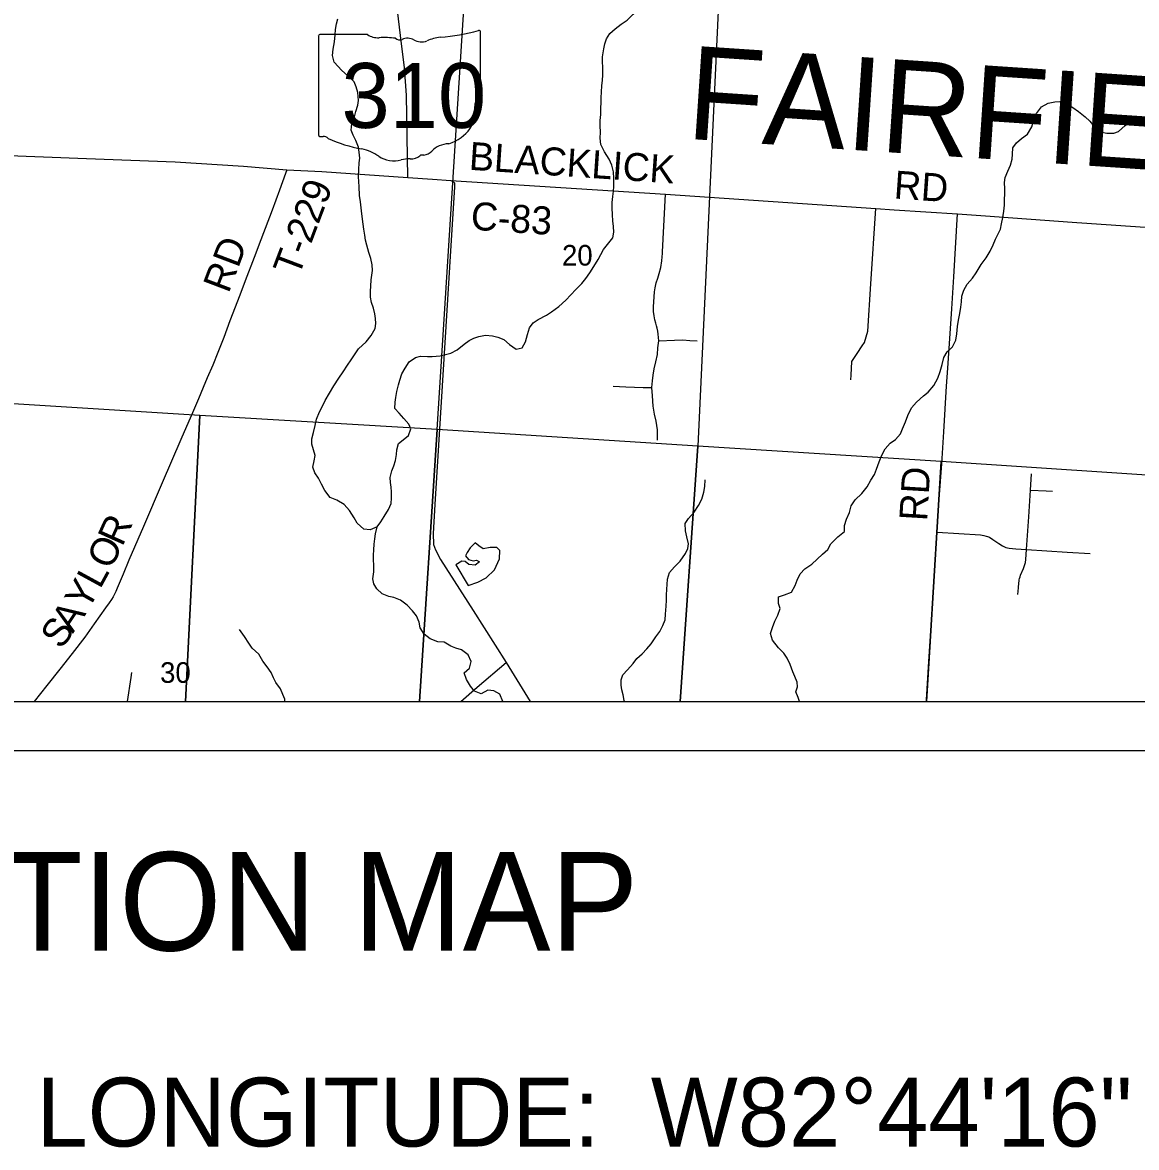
# Model space of a CAD drawing. Extents: x 0 to 34, y 0 to 22.
# Drawn here: x 5.197 to 7.46, y 13.194 to 15.479 of the extents above; entities that cross this region are included whole.
import ezdxf

# ---------------------------------------------------------------- set-up
doc = ezdxf.new("R2010")
doc.units = 0
for name, color, linetype in [('GM_X_Corporation', 7, 'Continuous'), ('GM_X_County_Road', 7, 'Continuous'), ('GM_X_County_Road_Text', 7, 'Continuous'), ('GM_X_County_Text', 7, 'Continuous'), ('GM_X_Minor_Lake', 7, 'Continuous'), ('GM_X_Minor_River', 7, 'Continuous'), ('GM_X_Section', 7, 'Continuous'), ('GM_X_Section_Text', 7, 'Continuous'), ('GM_X_State_Location', 7, 'Continuous'), ('GM_X_State_Route', 7, 'Continuous'), ('GM_X_State_Shield', 7, 'Continuous'), ('GM_X_Township_Road', 7, 'Continuous'), ('GM_X_Township_Road_Text', 7, 'Continuous'), ('GM_X_Unincorporated_Text', 7, 'Continuous'), ('SH_Cut_Line', 7, 'Continuous'), ('SH_Data', 7, 'Continuous'), ('SH_Text', 7, 'Continuous')]:
    doc.layers.add(name, color=color, linetype=linetype)

msp = doc.modelspace()

# ---------------------------------------------------------------- linework, layer by layer
at = {"layer": 'GM_X_Corporation'}
msp.add_lwpolyline([(4.9875, 14.1), (8.9, 14.1), (8.9, 15.4827), (8.6741, 15.4976), (7.6503, 15.5653), (6.838, 15.6206), (6.624, 15.6351), (6.4, 15.6498), (6.1109, 15.6683), (5.9419, 15.6782), (5.0952, 15.7318), (5.0611, 15.2147)], close=True, dxfattribs=at)
at = {"layer": 'GM_X_County_Road'}
msp.add_lwpolyline([(6.0671, 15.1581), (6.5033, 15.13), (6.9303, 15.1012), (6.9673, 15.0987), (7.0963, 15.09), (7.1532, 15.0863), (7.3292, 15.0734), (7.3386, 15.0729), (7.3489, 15.0722), (7.5961, 15.0553), (7.606, 15.0546), (7.6158, 15.0539), (7.8422, 15.0387), (7.8505, 15.0381), (7.8619, 15.0373), (8.1079, 15.0203), (8.1178, 15.0196), (8.3992, 15.0045), (8.635, 14.9861)], dxfattribs=at)
at = {"layer": 'GM_X_Minor_Lake'}
for points in [[(6.102, 14.3357), (6.1218, 14.3423), (6.1389, 14.3513), (6.1554, 14.367), (6.1658, 14.3893), (6.1664, 14.4064), (6.16, 14.4129), (6.1468, 14.4123), (6.1323, 14.4102), (6.1237, 14.416), (6.1162, 14.4221), (6.1062, 14.412), (6.1001, 14.4025), (6.0966, 14.3954), (6.1026, 14.3881), (6.112, 14.3857), (6.1188, 14.3872), (6.1249, 14.3833), (6.1161, 14.3769), (6.1032, 14.3782), (6.0957, 14.384), (6.0889, 14.3848), (6.0771, 14.3777)], [(6.0771, 14.3777), (6.102, 14.3357)]]:
    msp.add_lwpolyline(points, dxfattribs=at)
at = {"layer": 'GM_X_Minor_River'}
for points in [[(6.3752, 15.3987), (6.3749, 15.409), (6.3774, 15.4253), (6.3798, 15.4355), (6.3833, 15.4457), (6.3902, 15.4563), (6.4009, 15.466), (6.4132, 15.4758), (6.4254, 15.484), (6.4372, 15.496), (6.4472, 15.5043), (6.4594, 15.514), (6.4603, 15.5269), (6.4574, 15.5379), (6.4556, 15.5482), (6.455, 15.5592), (6.4547, 15.5687), (6.4544, 15.579), (6.4549, 15.5892), (6.4554, 15.5987), (6.4548, 15.6101), (6.4534, 15.6204), (6.448, 15.6404)], [(5.9173, 14.4545), (5.9028, 14.4482), (5.8903, 14.4499), (5.8764, 14.4618), (5.8705, 14.4729), (5.8608, 14.4878), (5.8503, 14.5), (5.8349, 14.5085), (5.8217, 14.5144), (5.8109, 14.5282), (5.8042, 14.5415), (5.7979, 14.5533), (5.7908, 14.5644), (5.7867, 14.5755), (5.7892, 14.5887), (5.7912, 14.5993), (5.7875, 14.6111), (5.7842, 14.6226), (5.7847, 14.6336), (5.7879, 14.6464), (5.7915, 14.6604), (5.7942, 14.6733), (5.7997, 14.6881), (5.8051, 14.6983), (5.8117, 14.7111), (5.8202, 14.7262), (5.8291, 14.7409), (5.8395, 14.7564), (5.8483, 14.7692), (5.8572, 14.7831), (5.8645, 14.7941), (5.8722, 14.8057), (5.8795, 14.8163), (5.8948, 14.8306), (5.9052, 14.8434), (5.9129, 14.8577), (5.9145, 14.8679), (5.9135, 14.8774), (5.9121, 14.8869), (5.9099, 14.8987), (5.9059, 14.9102), (5.9037, 14.9212), (5.9035, 14.9333), (5.904, 14.9432), (5.9053, 14.9565), (5.9065, 14.9659), (5.9074, 14.9754), (5.9067, 14.9868), (5.9042, 14.9998), (5.9005, 15.0116), (5.8962, 15.0264), (5.8936, 15.0371), (5.8918, 15.0469), (5.8901, 15.0595), (5.8887, 15.069), (5.8876, 15.0796), (5.8852, 15.0967), (5.8831, 15.115), (5.8813, 15.1275), (5.8804, 15.1461), (5.8797, 15.1556), (5.8791, 15.1663), (5.88, 15.1807), (5.8809, 15.1936), (5.8818, 15.2034), (5.8804, 15.2156), (5.879, 15.2259), (5.8735, 15.2396), (5.8683, 15.2503), (5.8642, 15.2602), (5.8659, 15.2735), (5.8705, 15.2844), (5.8741, 15.2984), (5.878, 15.3109), (5.8789, 15.3204), (5.8779, 15.3371), (5.8746, 15.3485), (5.8702, 15.3581), (5.8567, 15.3711), (5.8451, 15.3815), (5.8301, 15.3983), (5.8264, 15.4121), (5.8277, 15.4249), (5.8302, 15.4397), (5.8318, 15.4541), (5.8327, 15.4644), (5.8343, 15.4761), (5.8371, 15.4867)], [(5.9107, 14.4079), (5.9108, 14.4197), (5.9121, 14.4299), (5.9137, 14.4405), (5.9173, 14.4545), (5.9246, 14.4647), (5.9315, 14.4753), (5.94, 14.4896), (5.9454, 14.5017), (5.9463, 14.5131), (5.9461, 14.5256), (5.9454, 14.5351), (5.9444, 14.5446), (5.9437, 14.5545), (5.9473, 14.5681), (5.9508, 14.5787), (5.9547, 14.5893), (5.9564, 14.6014), (5.9568, 14.6109), (5.9608, 14.6241), (5.9703, 14.6316), (5.981, 14.6402), (5.9857, 14.6535), (5.9817, 14.663), (5.9712, 14.6745), (5.9622, 14.6856), (5.9528, 14.6952), (5.9537, 14.7081), (5.9553, 14.7176), (5.9574, 14.7297), (5.9605, 14.7429), (5.9633, 14.7528), (5.9676, 14.7653), (5.9742, 14.777), (5.9819, 14.7894), (5.9949, 14.7988), (6.0051, 14.8009), (6.0191, 14.8004), (6.0286, 14.8007), (6.0453, 14.802), (6.0563, 14.8046), (6.0665, 14.8075), (6.0795, 14.8138), (6.094, 14.8254), (6.1043, 14.8329), (6.1138, 14.8378), (6.1237, 14.8411), (6.1374, 14.8436), (6.1514, 14.8423), (6.162, 14.8395), (6.1744, 14.8348), (6.1861, 14.8252), (6.1996, 14.8152), (6.2117, 14.8181), (6.2187, 14.8306), (6.2223, 14.8454), (6.227, 14.859), (6.2343, 14.8688), (6.2446, 14.8755), (6.2613, 14.8848), (6.2716, 14.8911), (6.2861, 14.9024), (6.3003, 14.9148), (6.321, 14.9366), (6.3332, 14.9486), (6.3409, 14.9591), (6.3494, 14.9704), (6.3575, 14.9836), (6.3663, 14.9976), (6.3772, 15.018), (6.3849, 15.0281), (6.396, 15.0413), (6.398, 15.0534), (6.397, 15.0648), (6.396, 15.0758), (6.3954, 15.088), (6.3947, 15.1024), (6.3949, 15.1134), (6.3958, 15.1252), (6.3974, 15.1366), (6.3983, 15.146), (6.398, 15.1624), (6.397, 15.1753), (6.3938, 15.189), (6.3886, 15.2016), (6.3793, 15.2165), (6.3715, 15.231), (6.3701, 15.2443), (6.3706, 15.2564), (6.3704, 15.2689), (6.3705, 15.2796), (6.3714, 15.2921), (6.3719, 15.305), (6.3724, 15.3164), (6.3725, 15.3266), (6.373, 15.3376), (6.3736, 15.3513), (6.3748, 15.3608), (6.3757, 15.3725), (6.3755, 15.3892), (6.3752, 15.3987)], [(7.0274, 14.7208), (7.037, 14.7279), (7.0485, 14.7418), (7.0562, 14.7565), (7.0613, 14.7698), (7.0652, 14.7845), (7.0684, 14.7982), (7.075, 14.8102), (7.0861, 14.82), (7.0927, 14.8336), (7.0951, 14.8468), (7.096, 14.8613), (7.0984, 14.8741), (7.1008, 14.8878), (7.1029, 14.901), (7.1045, 14.9113), (7.1054, 14.923), (7.1089, 14.9355), (7.1159, 14.9472), (7.1266, 14.9596), (7.1339, 14.9702), (7.1443, 14.9875), (7.1543, 15.0007), (7.1628, 15.0147), (7.169, 15.0275), (7.1737, 15.0389), (7.1787, 15.0494), (7.1834, 15.0593), (7.1857, 15.0702), (7.1882, 15.0831), (7.1902, 15.096), (7.1915, 15.1081), (7.192, 15.1203), (7.1925, 15.1305), (7.1926, 15.1412), (7.192, 15.1541), (7.1932, 15.1639), (7.1983, 15.1768), (7.2037, 15.1889), (7.2076, 15.2014), (7.2081, 15.2112), (7.209, 15.2245), (7.2159, 15.2347), (7.2263, 15.2433), (7.2385, 15.2523), (7.2473, 15.267), (7.2517, 15.2833), (7.2567, 15.2942), (7.2667, 15.3074), (7.2808, 15.3149), (7.2937, 15.3181), (7.304, 15.3188), (7.316, 15.3152), (7.3303, 15.3064), (7.342, 15.2983), (7.3555, 15.2875), (7.3653, 15.2787), (7.3761, 15.2653), (7.3897, 15.256), (7.3999, 15.254), (7.4139, 15.2542), (7.4234, 15.2576), (7.4368, 15.2699), (7.4501, 15.2801), (7.4626, 15.2735)], [(6.7754, 14.1), (6.7727, 14.1082), (6.7675, 14.1192), (6.7714, 14.1294), (6.7708, 14.1389), (6.766, 14.1508), (6.7615, 14.1603), (6.756, 14.1752), (6.7505, 14.1877), (6.7437, 14.1977), (6.7325, 14.2088), (6.7206, 14.2245), (6.7161, 14.2378), (6.7201, 14.2499), (6.7248, 14.2628), (6.7309, 14.2749), (6.736, 14.2885), (6.7327, 14.2991), (6.7325, 14.3124), (6.745, 14.3165), (6.7587, 14.322), (6.7664, 14.3356), (6.7703, 14.3462), (6.7766, 14.3594), (6.7861, 14.3692), (6.8002, 14.3785), (6.8113, 14.3886), (6.8221, 14.3992), (6.8331, 14.4085), (6.8386, 14.4199), (6.8531, 14.4345), (6.8665, 14.445), (6.867, 14.4575), (6.8709, 14.47), (6.8771, 14.4836), (6.8799, 14.4972), (6.8884, 14.5093), (6.9022, 14.5224), (6.9126, 14.536), (6.9199, 14.5492), (6.9276, 14.5609), (6.9319, 14.5715), (6.937, 14.5866), (6.9424, 14.6002), (6.949, 14.6127), (6.9593, 14.6243), (6.9704, 14.6318), (6.9804, 14.6438), (6.9847, 14.6537), (6.9905, 14.6676), (6.9952, 14.6805), (7.0025, 14.696), (7.0129, 14.708), (7.0274, 14.7208)], [(6.4195, 14.1), (6.4188, 14.102), (6.4167, 14.113), (6.4145, 14.1233), (6.4127, 14.1328), (6.4128, 14.1438), (6.4164, 14.1537), (6.4256, 14.1638), (6.4374, 14.177), (6.4447, 14.1868), (6.4555, 14.1965), (6.465, 14.2067), (6.4739, 14.2168), (6.4831, 14.2311), (6.4912, 14.2421), (6.4977, 14.2545), (6.502, 14.2655), (6.5033, 14.2769), (6.5046, 14.2935), (6.5047, 14.3053), (6.5052, 14.3156), (6.5057, 14.3277), (6.5066, 14.3372), (6.5071, 14.3486), (6.511, 14.3618), (6.521, 14.3735), (6.5325, 14.3847), (6.5436, 14.4006), (6.5487, 14.4107), (6.5495, 14.4202), (6.5463, 14.4343), (6.5434, 14.4465), (6.5432, 14.4613), (6.5497, 14.4718), (6.5612, 14.4846), (6.5701, 14.4982), (6.5767, 14.511), (6.5806, 14.5247), (6.583, 14.5364), (6.5835, 14.5501)], [(6.1726, 14.1), (6.1667, 14.1145), (6.1542, 14.1215), (6.1421, 14.1231), (6.1288, 14.1157), (6.1148, 14.1211), (6.107, 14.1307), (6.0988, 14.1445), (6.0936, 14.1578), (6.1047, 14.1672), (6.1079, 14.1808), (6.102, 14.1945), (6.0885, 14.2049), (6.0768, 14.2081), (6.0666, 14.2123), (6.053, 14.2201), (6.0402, 14.221), (6.0251, 14.2268), (6.0127, 14.2364), (6.0048, 14.2494), (6.0023, 14.2608), (5.9972, 14.2738), (5.9889, 14.2838), (5.9781, 14.2956), (5.9649, 14.3056), (5.9513, 14.3107), (5.9411, 14.3131), (5.9276, 14.3182), (5.9163, 14.3289), (5.9103, 14.3389), (5.9086, 14.3487), (5.9102, 14.3635), (5.9104, 14.3772), (5.9097, 14.3867), (5.9098, 14.3969), (5.9107, 14.4079)], [(5.7297, 14.1), (5.7294, 14.1043), (5.7257, 14.1142), (5.7205, 14.1253), (5.7116, 14.1386), (5.7068, 14.1482), (5.7016, 14.1589), (5.6934, 14.1699), (5.6852, 14.1818), (5.6766, 14.1959), (5.6635, 14.2078), (5.6564, 14.2185), (5.6478, 14.2319), (5.6377, 14.2457)]]:
    msp.add_lwpolyline(points, dxfattribs=at)
at = {"layer": 'GM_X_Section'}
msp.add_lwpolyline([(6.1034, 15.6668), (6.6161, 15.6333), (6.5689, 14.6183), (6.0392, 14.6526)], close=True, dxfattribs=at)
at = {"layer": 'GM_X_State_Route'}
msp.add_line((6.1793, 14.1792), (6.2278, 14.1), dxfattribs=at)
for points in [[(5.9797, 15.1639), (5.9768, 15.3312), (5.9727, 15.3868), (5.9649, 15.4526), (5.9506, 15.5715), (5.9421, 15.6777)], [(4.5623, 15.2529), (4.6682, 15.2448), (4.9129, 15.226), (5.0613, 15.2142), (5.1521, 15.2093), (5.3266, 15.2026), (5.5066, 15.1961), (5.6457, 15.1869), (5.7333, 15.1799), (5.8049, 15.1761), (5.9797, 15.1639)], [(5.9797, 15.1639), (6.0299, 15.1607), (6.0671, 15.1581), (6.0731, 15.1548), (6.074, 15.1532), (6.0745, 15.1516), (6.0746, 15.148), (6.0746, 15.1442), (6.0675, 15.0371), (6.0342, 14.4996), (6.031, 14.4408), (6.0314, 14.4188), (6.0354, 14.4076), (6.0458, 14.3884), (6.1121, 14.2847), (6.1793, 14.1792)]]:
    msp.add_lwpolyline(points, dxfattribs=at)
at = {"layer": 'GM_X_State_Shield'}
for p, q in [((5.7977, 15.4509), (5.7977, 15.2507)), ((5.8974, 15.4543), (5.8009, 15.4543)), ((6.1272, 15.3546), (6.1272, 15.4593)), ((6.1272, 15.3546), (6.1272, 15.3546))]:
    msp.add_line(p, q, dxfattribs=at)
for centre, major_axis, start_param, end_param in [((5.8014, 15.4513), (0.00382, 0), 1.712693, 3.28349), ((5.9204, 15.4775), (0.037, 0), 4.042523, 4.731795), ((5.9327, 15.342), (0.133, 0), 1.404758, 1.657858), ((5.9786, 15.4292), (0.0222, 0), 0.950623, 2.079405), ((6.0544, 15.3932), (0.0703, 0), 1.699011, 2.107814), ((6.0098, 15.7271), (0.3495, 0), 4.814394, 5.042369), ((6.1236, 15.4597), (0.00367, 0), 6.141152, 7.989035), ((5.9629, 15.4523), (0.0107, 0), 3.836095, 5.185415), ((6.0072, 15.4609), (0.0267, 0), 4.081561, 5.145723), ((6.1264, 15.3469), (0.00568, 0), 1.883978, 3.671073), ((6.0903, 15.3337), (0.0341, 0), 5.934695, 6.695948), ((6.1233, 15.3542), (0.00393, 0), 5.05454, 6.418171), ((6.1404, 15.3108), (0.0248, 0), 2.387724, 3.262537), ((6.0294, 15.2974), (0.0874, 0), 5.101752, 6.440018), ((5.8015, 15.2503), (0.00385, 0), 3.00124, 4.508301), ((5.8021, 15.2708), (0.0294, 0), 4.665946, 4.897461), ((5.8081, 15.2392), (0.0106, 0), 0.519207, 1.627899), ((5.9419, 15.419), (0.2524, 0), 4.195997, 4.488961), ((5.8666, 15.1608), (0.079, 0), 0.823519, 1.323587), ((6.0663, 15.1946), (0.0479, 0), 1.647645, 2.488434), ((5.9521, 15.2382), (0.0501, 0), 4.026481, 4.996735), ((5.981, 15.169), (0.0412, 0), 1.495662, 1.94098), ((5.9847, 15.2232), (0.0267, 0), 4.691044, 5.507374), ((6.0088, 15.2038), (0.00752, 0), 1.147584, 2.315152), ((6.0056, 15.2313), (0.0282, 0), 4.937069, 5.64225)]:
    msp.add_ellipse(centre, major_axis=major_axis, ratio=0.8, start_param=start_param, end_param=end_param, dxfattribs=at)
at = {"layer": 'GM_X_Township_Road'}
msp.add_line((6.4972, 15.0131), (6.5033, 15.13), dxfattribs=at)
for points in [[(5.7333, 15.1799), (5.7309, 15.1725), (5.7184, 15.1386), (5.7036, 15.098), (5.6806, 15.0372), (5.6672, 15.0019), (5.6491, 14.9545), (5.6379, 14.9251), (5.6181, 14.8727), (5.6056, 14.8393), (5.5935, 14.8086), (5.5834, 14.783), (5.5721, 14.7575), (5.5636, 14.7374), (5.5541, 14.7145), (5.5418, 14.6861), (5.5342, 14.6691), (5.5183, 14.632), (5.4802, 14.5437), (5.4426, 14.4552), (5.4129, 14.3869), (5.4008, 14.3583), (5.3891, 14.3302), (5.3861, 14.3231), (5.3838, 14.3177), (5.3807, 14.3122), (5.3772, 14.3071), (5.3724, 14.3004), (5.3655, 14.29), (5.342, 14.2576), (5.3231, 14.2307), (5.2977, 14.1971), (5.2726, 14.1658), (5.246, 14.1323), (5.2331, 14.116), (5.2202, 14.1)], [(6.8794, 14.7529), (6.88, 14.7623), (6.8819, 14.7907), (6.8923, 14.8065), (6.9029, 14.8222), (6.9076, 14.8291), (6.9138, 14.8523), (6.9199, 14.948), (6.9303, 15.1012)], [(7.033, 14.1), (7.0332, 14.1033), (7.0377, 14.181), (7.042, 14.243), (7.046, 14.305), (7.0507, 14.3795), (7.0552, 14.4439), (7.0593, 14.5113), (7.0641, 14.5824), (7.0683, 14.6474), (7.0739, 14.7401), (7.0769, 14.7771), (7.0845, 14.8971), (7.0886, 14.9621), (7.0963, 15.09)], [(6.4869, 14.6303), (6.4869, 14.6516), (6.4841, 14.669), (6.4806, 14.6833), (6.4778, 14.6995), (6.4763, 14.7207), (6.475, 14.7373), (6.4763, 14.7508), (6.4778, 14.7628), (6.4797, 14.7756), (6.4831, 14.7898), (6.4864, 14.8049), (6.4875, 14.8182), (6.4892, 14.8325), (6.4885, 14.8392), (6.4884, 14.8459), (6.4871, 14.8519), (6.4858, 14.8581), (6.4848, 14.863), (6.4831, 14.8683), (6.4816, 14.8749), (6.4798, 14.8832), (6.4784, 14.892), (6.4786, 14.9014), (6.4793, 14.9117), (6.4797, 14.9217), (6.4807, 14.9319), (6.482, 14.9399), (6.4843, 14.9499), (6.4873, 14.9598), (6.4902, 14.9694), (6.4932, 14.9814), (6.4956, 14.9949), (6.4965, 15.0033), (6.497, 15.01), (6.4972, 15.0131)], [(6.4892, 14.8325), (6.5213, 14.834), (6.538, 14.8342), (6.5527, 14.8333), (6.5676, 14.8324)], [(6.3965, 14.7406), (6.4222, 14.739), (6.4576, 14.7376), (6.475, 14.7373)], [(7.219, 14.3168), (7.2201, 14.3306), (7.221, 14.3408), (7.2213, 14.344), (7.2218, 14.347), (7.2224, 14.3499), (7.2233, 14.353), (7.2245, 14.3561), (7.2305, 14.3702), (7.2327, 14.376), (7.2343, 14.382), (7.2353, 14.3881), (7.2366, 14.4085), (7.241, 14.475), (7.2444, 14.5293), (7.2464, 14.5619)], [(7.2444, 14.5293), (7.2766, 14.5276), (7.289, 14.5271)], [(7.0552, 14.4439), (7.1433, 14.4381), (7.1495, 14.4373), (7.1544, 14.4359)], [(7.1544, 14.4359), (7.1573, 14.4351), (7.1612, 14.4334), (7.1682, 14.4291), (7.18, 14.4205), (7.1878, 14.4158), (7.1948, 14.4127), (7.2015, 14.4114), (7.2148, 14.4099), (7.2366, 14.4085), (7.319, 14.403), (7.3655, 14.4001)], [(6.0871, 14.1), (6.1204, 14.1288), (6.1793, 14.1792)], [(5.4099, 14.1), (5.4172, 14.1487), (5.4187, 14.1586)]]:
    msp.add_lwpolyline(points, dxfattribs=at)
at = {"layer": 'GM_X_Unincorporated_Text'}
for points in [[(4.9875, 14.1), (5.5277, 14.1), (5.5568, 14.6807), (5.0255, 14.7138)], [(5.5277, 14.1), (6.0032, 14.1), (6.0392, 14.6526), (5.5568, 14.6807)], [(6.0032, 14.1), (6.5325, 14.1), (6.5689, 14.6183), (6.0392, 14.6526)], [(6.5325, 14.1), (7.0331, 14.1), (7.0634, 14.5876), (6.5689, 14.6183)], [(7.0331, 14.1), (7.5731, 14.1), (7.6037, 14.5512), (7.0634, 14.5876)]]:
    msp.add_lwpolyline(points, close=True, dxfattribs=at)
at = {"layer": 'SH_Cut_Line'}
msp.add_lwpolyline([(2.1, 15.9442), (2.1, 14.1), (8.9, 14.1), (8.9, 15.4827), (8.6741, 15.4976), (7.6503, 15.5653), (6.838, 15.6206), (6.624, 15.6351), (6.4, 15.6498), (6.1109, 15.6683), (5.9419, 15.6782), (5.0952, 15.7318), (4.92, 15.7429), (4.5905, 15.7634), (4.2803, 15.787), (3.9945, 15.8088), (3.3132, 15.8609), (2.8362, 15.8952), (2.7799, 15.8989), (2.6921, 15.9056), (2.5827, 15.9132), (2.2903, 15.9292)], close=True, dxfattribs=at)
at = {"layer": 'SH_Data'}
msp.add_line((2, 14), (9, 14), dxfattribs=at)

# ---------------------------------------------------------------- texts
at = {"layer": 'GM_X_County_Road_Text'}
for s, rotation, p in [('BLACKLICK', 356.1538, (6.1026, 15.1799)), ('RD', 356.0533, (6.9659, 15.1216)), ('C-83', 356.2083, (6.1062, 15.0583))]:
    msp.add_text(s, height=0.05682, rotation=rotation, dxfattribs=at).set_placement(p)
at = {"layer": 'GM_X_County_Text'}
msp.add_text('FAIRFIELD COUNTY', height=0.189394, rotation=356.1646, dxfattribs=at).set_placement((6.5431, 15.243))
at = {"layer": 'GM_X_Section_Text'}
for s, p in [('20', (6.2927, 14.9852)), ('30', (5.4761, 14.1377))]:
    msp.add_text(s, height=0.04186, rotation=0, dxfattribs=at).set_placement(p)
at = {"layer": 'GM_X_State_Location'}
for s, p in [('s', (5.9588, 15.3375)), ('r', (5.9587, 15.3375))]:
    msp.add_text(s, height=0.000189, dxfattribs=at).set_placement(p)
msp.add_text('310', height=0.000189, rotation=0, dxfattribs=at).set_placement((5.8919, 15.3237))
at = {"layer": 'GM_X_State_Shield'}
msp.add_text('310', height=0.13184, dxfattribs=at).set_placement((5.8446, 15.2648))
at = {"layer": 'GM_X_Township_Road_Text'}
for s, height, rotation, p in [('T-229', 0.05682, 69.3908, (5.7576, 14.9607)), ('RD', 0.05682, 69.2732, (5.6152, 14.9272)), ('RD', 0.05682, 86.5769, (7.0346, 14.4654)), ('R', 0.0568, 65.8019, (5.3993, 14.4127)), ('O', 0.0568, 63.1676, (5.3755, 14.3655)), ('Y', 0.0568, 60.3824, (5.329, 14.2821)), ('L', 0.0568, 61.3555, (5.3542, 14.3265)), ('A', 0.0568, 56.3143, (5.2989, 14.2368)), ('S', 0.0568, 54.0177, (5.275, 14.2037))]:
    msp.add_text(s, height=height, rotation=rotation, dxfattribs=at).set_placement(p)
at = {"layer": 'SH_Text'}
for s, height, p in [('LOCATION MAP', 0.2, (4.4269, 13.5938)), ('LATITUDE:  N39°57\'5"     LONGITUDE:  W82°44\'16"', 0.14, (3.071, 13.1959))]:
    msp.add_text(s, height=height, dxfattribs=at).set_placement(p)

doc.saveas('drawing.dxf')
